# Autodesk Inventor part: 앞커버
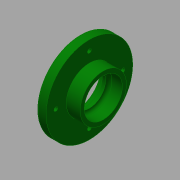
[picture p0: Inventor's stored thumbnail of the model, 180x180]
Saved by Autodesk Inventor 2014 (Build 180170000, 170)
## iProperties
Created: 2015-09
Part Number: 앞커버
Material: 알루미늄 6061
Document SubType Name: Modeling
Designer: mduedu
Density: 2.71 g/cm^3
Mass: 58.9874 g
Surface Area: 98.7754 cm^2
Volume: 21.7666 cm^3
Appearance: Dark Green
Author: mduedu
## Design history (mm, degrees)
sketch "스케치1"
  geometry: L1 (-4, 67)-(-16, 67); L2 (-16, 67)-(-16, 84.5); L3 (-16, 84.5)-(-24, 84.5); L4 (-24, 84.5)-(-24, 70.5); L5 (-27, 70.5)-(-27, 61); L6 (-27, 61)-(-4, 61); L7 (-4, 61)-(-4, 67); L8 (-79.5, 39.5)-(-79.5, 54.5) reference; L9 (48.5, 54.5)-(48.5, 39.5) reference; L10 (-79.5, 47)-(48.5, 47); L11 (-24, 70.5)-(-27, 70.5); 3 further points
  constraints: 18 end point, 6 parallel, 4 midpoint, 1 horizontal, 1 perpendicular, 1 vertical alignment
  dimensions: "d0" = 23 distance between parallel lines of L7 L5; "d2" = 28 diameter of L6 L10; "d3" = 40 diameter of L1 L10; "d5" = 12 distance of L1.start L1.end; "d6" = 75 diameter of L3 L10; "d7" = 8 distance of L2.end L3.end; "d8" = 47 diameter of L4.end L10
revolve "회전1" sketch "스케치1" stored, may be unused: angle "d4" = 90 deg
sketch "스케치2"
  geometry: C1 r 37.5 at (0, 0) reference; 2 further points
  constraints: 1 coincident
hole "구멍1" sketch "스케치2" at (0, 0) diameter "d11" = 33; stored, may be unused: countersink angle "d15" = 90 deg, drill point angle "d17" = 0 deg; dims "d12" = 6, "d13" = 4, "d14" = 2, "d16" = 12
fillet "모깎기1" dims "d18" = 3
fillet "모깎기2" dims "d19" = 1
sketch "스케치3"
  geometry: C1 r 37.5 at (0, 0) reference; 2 further points
  constraints: 1 coincident
hole "구멍2" sketch "스케치3" at (0, 0) diameter "d20" = 40; stored, may be unused: countersink angle "d24" = 90 deg, drill point angle "d26" = 0 deg; dims "d21" = 6, "d22" = 4, "d23" = 2, "d25" = 8
fillet "모깎기3" dims "d27" = 0.4
chamfer "모따기1" distance "d28" = 1; stored, may be unused: second distance "d29" = 2, angle "d30" = 30 deg
sketch "스케치7" dims "d56" = 58
  geometry: C1 r 37.5 at (0, 0) reference; 5 further points
  constraints: 2 vertical alignment, 1 coincident, 7 other
  dimensions: "d59" = 360 deg dimension on C1.centre point (0, 29) (derived)
hole "구멍4" sketch "스케치7" at (0, 29), (-29, 0), (0, -29), (29, 0) diameter "d48" = 3.4; stored, may be unused: countersink angle "d52" = 90 deg, drill point angle "d54" = 0 deg; dims "d49" = 6, "d50" = 6.5, "d51" = 3.4, "d53" = 8
node "솔리드1"
node "참조1"
node "참조2"
